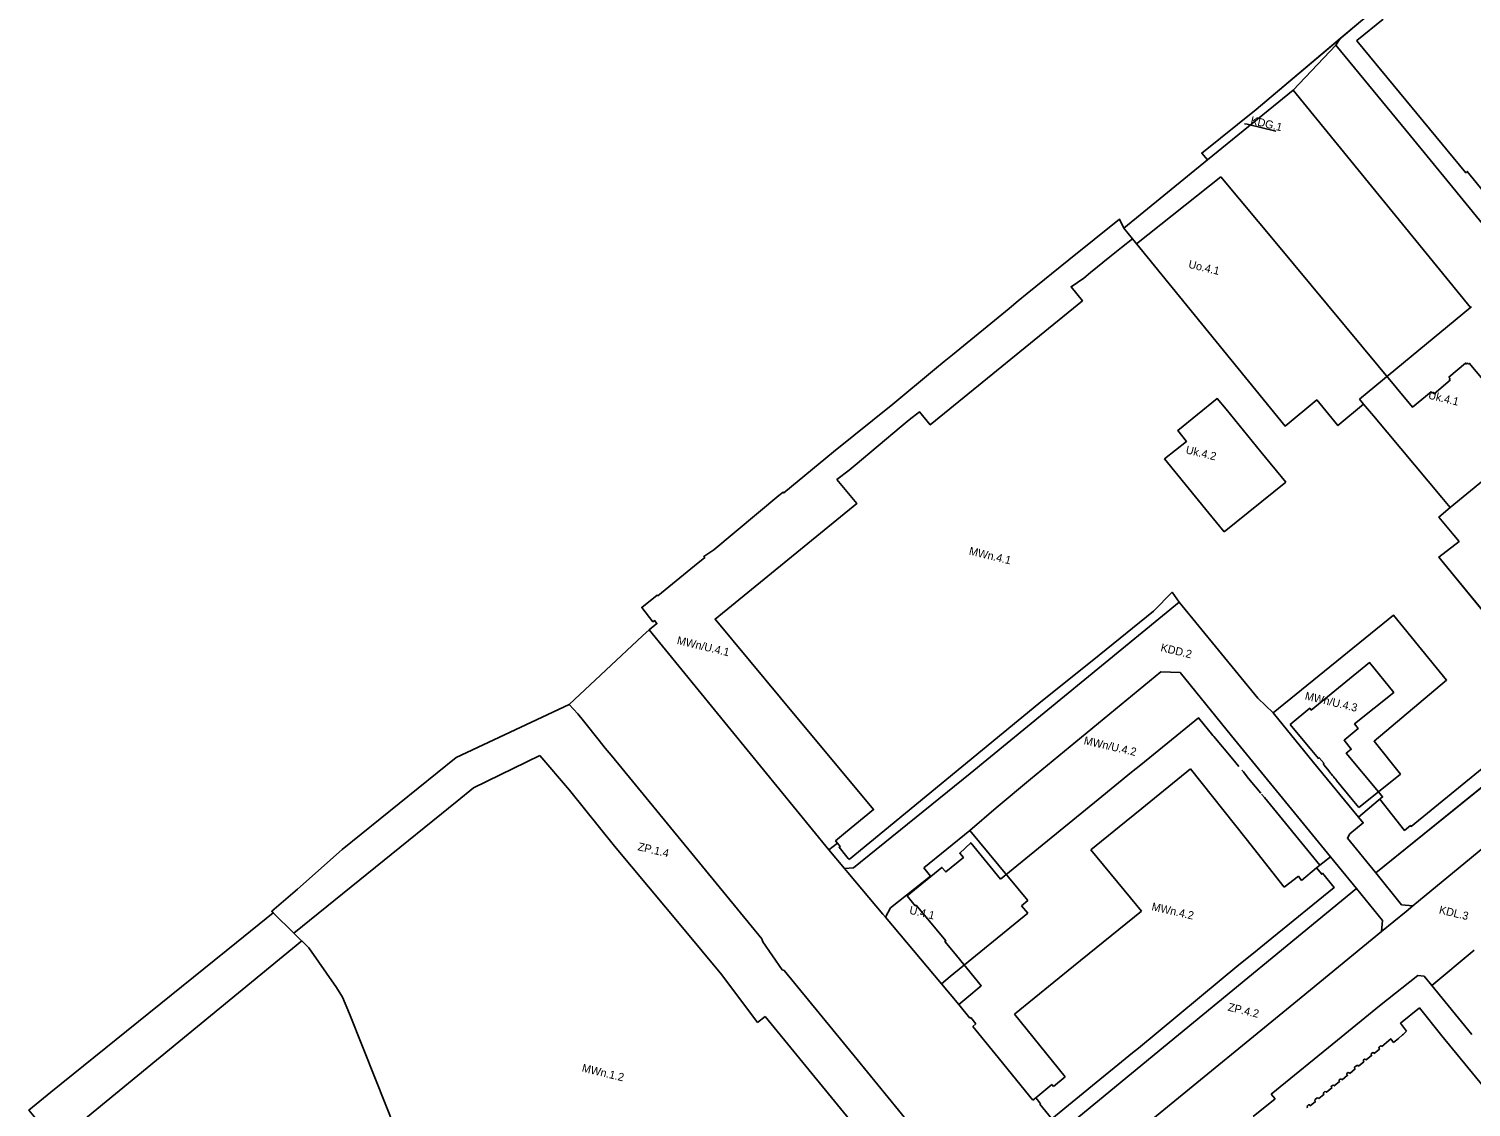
# Model space of a CAD drawing. Extents: x 7429686 to 7432896, y 5547954 to 5550600.
# Drawn here: x 7430132 to 7430853, y 5549462 to 5550001 of the extents above; entities that cross this region are included whole.
import ezdxf

# ---------------------------------------------------------------- set-up
doc = ezdxf.new("R2010")
doc.units = 0
for name, color, linetype in [('granica planu', 7, 'Continuous'), ('linie rozgraniczające', 7, 'Continuous'), ('obowiązująca linia zabudowy', 7, 'Continuous'), ('oznaczenia przeznaczeń', 7, 'Continuous')]:
    doc.layers.add(name, color=color, linetype=linetype)

msp = doc.modelspace()

# ---------------------------------------------------------------- linework, layer by layer
at = {"layer": 'granica planu'}
for p, q in [((7430679.88, 5549901.24), (7430721.7, 5549935.43)), ((7430721.7, 5549935.43), (7430718.8, 5549938.87)), ((7430652.39, 5549885.51), (7430677.58, 5549905.8)), ((7430677.58, 5549905.8), (7430679.88, 5549901.24)), ((7430623.59, 5549862.1), (7430627, 5549864.89)), ((7430594.17, 5549837.99), (7430622.47, 5549861.18)), ((7430622.47, 5549861.18), (7430623.59, 5549862.1)), ((7430589.98, 5549834.54), (7430594.17, 5549837.99)), ((7430534.74, 5549789.36), (7430564.34, 5549813.28)), ((7430509.79, 5549768.85), (7430534.74, 5549789.36)), ((7430509.45, 5549769.31), (7430509.79, 5549768.85)), ((7430474.76, 5549740.46), (7430507.29, 5549767.5)), ((7430469.8, 5549737.01), (7430474.76, 5549740.46)), ((7430445.21, 5549704.96), (7430444.4, 5549704.41)), ((7430345.97, 5549636.49), (7430402.43, 5549663.1))]:
    msp.add_line(p, q, dxfattribs=at)
for points in [[(7430718.8, 5549938.87), (7430746.03, 5549960.72), (7430798.13, 5550004.59), (7430923.69, 5550106.91), (7431051.87, 5550217.85), (7431132.58, 5550281.48)], [(7430627, 5549864.89), (7430631.48, 5549868.55), (7430652.39, 5549885.51)], [(7430564.34, 5549813.28), (7430585.18, 5549830.6), (7430589.98, 5549834.54)], [(7430507.29, 5549767.5), (7430507.35, 5549767.54), (7430509.45, 5549769.31)], [(7430465.23, 5549732.34), (7430470.33, 5549736.47), (7430469.8, 5549737.01)], [(7430444.4, 5549704.41), (7430438.78, 5549711.57), (7430446.42, 5549717.73), (7430446.76, 5549717.38), (7430465.23, 5549732.34)], [(7430442.54, 5549700.35), (7430446.41, 5549703.48), (7430445.21, 5549704.96)], [(7430402.43, 5549663.1), (7430439.12, 5549697.39), (7430442.54, 5549700.35)], [(7430266.62, 5549570.67), (7430289.05, 5549590.5), (7430336.45, 5549628.86), (7430345.97, 5549636.49)], [(7430236.2, 5549543.95), (7430254.55, 5549558.75), (7430253.79, 5549559.57), (7430266.62, 5549570.67)], [(7430132.35, 5549460.15), (7430143.42, 5549469.09), (7430236.2, 5549543.95)]]:
    msp.add_lwpolyline(points, dxfattribs=at)
at = {"layer": 'linie rozgraniczające'}
for p, q in [((7430672.89, 5549886.9), (7430663.09, 5549879.13)), ((7430663.09, 5549879.13), (7430659.85, 5549876.29)), ((7430659.1, 5549864.98), (7430583.08, 5549802.87)), ((7430700.22, 5549785.83), (7430722.36, 5549758.75)), ((7430545.48, 5549782.66), (7430542.42, 5549780.28)), ((7430760.78, 5549774.19), (7430729.96, 5549749.47)), ((7430729.96, 5549749.47), (7430760.78, 5549774.19)), ((7430546.31, 5549763.55), (7430475.46, 5549705.76)), ((7430729.96, 5549749.47), (7430722.36, 5549758.75)), ((7430722.36, 5549758.75), (7430729.96, 5549749.47)), ((7430837.33, 5549756.8), (7430843.03, 5549761.55)), ((7430844.84, 5549747.74), (7430837.33, 5549756.8)), ((7430847.43, 5549744.63), (7430844.84, 5549747.74)), ((7430837.38, 5549736.73), (7430847.43, 5549744.63)), ((7430897.36, 5549663.3), (7430837.38, 5549736.73)), ((7430508.16, 5549666.42), (7430554.71, 5549610.46)), ((7430805.78, 5549578.76), (7430902.46, 5549657.05)), ((7430554.71, 5549610.46), (7430540.68, 5549599.07)), ((7430536.73, 5549593.64), (7430532.29, 5549590.32)), ((7430532.29, 5549590.32), (7430540.19, 5549580.93))]:
    msp.add_line(p, q, dxfattribs=at)
for points in [[(7430973.53, 5550150.05), (7430923.69, 5550106.91), (7430798.13, 5550004.59), (7430788.04, 5549996.1)], [(7430788.04, 5549996.1), (7430746.03, 5549960.72), (7430718.8, 5549938.87), (7430721.7, 5549935.43)], [(7430764.45, 5549970.37), (7430785.78, 5549992.89)], [(7430785.78, 5549992.89), (7430787.7, 5549995.61)], [(7430823.15, 5549947.46), (7430785.78, 5549992.89)], [(7430787.7, 5549995.61), (7430788.04, 5549996.1)], [(7430764.45, 5549970.37), (7430721.7, 5549935.43)], [(7430853.19, 5549861.61), (7430764.45, 5549970.37)], [(7430842.76, 5549923.45), (7430823.15, 5549947.46)], [(7430721.7, 5549935.43), (7430679.88, 5549901.24)], [(7430895.54, 5549859.01), (7430842.76, 5549923.45)], [(7430679.88, 5549901.24), (7430677.58, 5549905.8), (7430652.39, 5549885.51), (7430631.48, 5549868.55), (7430627, 5549864.89), (7430623.59, 5549862.1), (7430622.47, 5549861.18), (7430594.17, 5549837.99), (7430589.98, 5549834.54), (7430585.18, 5549830.6), (7430564.34, 5549813.28), (7430534.74, 5549789.36), (7430509.79, 5549768.85), (7430509.45, 5549769.31), (7430507.35, 5549767.54), (7430507.29, 5549767.5), (7430474.76, 5549740.46), (7430469.8, 5549737.01), (7430470.33, 5549736.47), (7430465.23, 5549732.34), (7430446.76, 5549717.38), (7430446.42, 5549717.73), (7430438.78, 5549711.57), (7430444.4, 5549704.41), (7430445.21, 5549704.96), (7430446.41, 5549703.48), (7430442.54, 5549700.35)], [(7430684.14, 5549896), (7430679.88, 5549901.24)], [(7430532.29, 5549590.32), (7430536.73, 5549593.64), (7430535.72, 5549594.81), (7430540.68, 5549599.07), (7430554.71, 5549610.46), (7430508.16, 5549666.42), (7430492.64, 5549685.07), (7430475.46, 5549705.76), (7430546.31, 5549763.55), (7430536.39, 5549775.56), (7430542.42, 5549780.28), (7430545.48, 5549782.66), (7430568.47, 5549802.15), (7430572.49, 5549805.46), (7430577.72, 5549809.41), (7430583.08, 5549802.87), (7430659.1, 5549864.98), (7430653.43, 5549871.99), (7430659.85, 5549876.29), (7430663.09, 5549879.13), (7430672.89, 5549886.9), (7430678.73, 5549891.62), (7430684.14, 5549896)], [(7430684.14, 5549896), (7430678.73, 5549891.62), (7430672.89, 5549886.9)], [(7430799.73, 5549813.23), (7430786.87, 5549802.53), (7430776.31, 5549815.35), (7430760.42, 5549802.31), (7430684.14, 5549896)], [(7430684.14, 5549896), (7430760.42, 5549802.31)], [(7430659.85, 5549876.29), (7430653.43, 5549871.99), (7430659.1, 5549864.98)], [(7430797.65, 5549815.78), (7430853.19, 5549861.61)], [(7430853.19, 5549861.61), (7430853.71, 5549862.02)], [(7430722.36, 5549758.75), (7430700.22, 5549785.83), (7430711.1, 5549794.65), (7430706.78, 5549800), (7430726.5, 5549816.04), (7430730.95, 5549810.8), (7430748.25, 5549789.4), (7430760.78, 5549774.19)], [(7430760.78, 5549774.19), (7430748.25, 5549789.4), (7430730.95, 5549810.8), (7430726.5, 5549816.04), (7430706.78, 5549800), (7430711.1, 5549794.65), (7430700.22, 5549785.83)], [(7430760.42, 5549802.31), (7430776.31, 5549815.35), (7430786.87, 5549802.53), (7430799.73, 5549813.23)], [(7430799.73, 5549813.23), (7430797.65, 5549815.78)], [(7430843.03, 5549761.55), (7430838.83, 5549766.56), (7430804.68, 5549807.34), (7430799.73, 5549813.23)], [(7430799.73, 5549813.23), (7430804.68, 5549807.34)], [(7430583.08, 5549802.87), (7430577.72, 5549809.41), (7430572.49, 5549805.46), (7430568.47, 5549802.15), (7430545.48, 5549782.66)], [(7430804.68, 5549807.34), (7430838.83, 5549766.56), (7430843.03, 5549761.55)], [(7430843.03, 5549761.55), (7430897.72, 5549806.4)], [(7430542.42, 5549780.28), (7430536.39, 5549775.56), (7430546.31, 5549763.55)], [(7430843.03, 5549761.55), (7430837.33, 5549756.8), (7430844.84, 5549747.74), (7430847.43, 5549744.63), (7430837.38, 5549736.73), (7430897.36, 5549663.3), (7430902.46, 5549657.05)], [(7430754.51, 5549658.77), (7430746.78, 5549666.21), (7430707.47, 5549714.16), (7430602.92, 5549628.54), (7430544.68, 5549581.29), (7430540.19, 5549580.93)], [(7430602.92, 5549628.54), (7430707.47, 5549714.16), (7430746.78, 5549666.21), (7430754.51, 5549658.77)], [(7430475.46, 5549705.76), (7430492.64, 5549685.07), (7430508.16, 5549666.42)], [(7430754.51, 5549658.77), (7430814.61, 5549707.76), (7430841.19, 5549675.26), (7430804.95, 5549644.67), (7430818.12, 5549628.18), (7430807.14, 5549619.41), (7430809.2, 5549616.83), (7430797.14, 5549606.69)], [(7430797.14, 5549606.69), (7430809.2, 5549616.83), (7430807.14, 5549619.41), (7430818.12, 5549628.18), (7430804.95, 5549644.67), (7430841.19, 5549675.26), (7430814.61, 5549707.76), (7430754.51, 5549658.77)], [(7430442.54, 5549700.35), (7430439.12, 5549697.39), (7430402.43, 5549663.1)], [(7430532.29, 5549590.32), (7430442.54, 5549700.35)], [(7430633.19, 5549625.63), (7430698.25, 5549679.36)], [(7430698.25, 5549679.36), (7430707.95, 5549679.01)], [(7430707.95, 5549679.01), (7430733.7, 5549647.43)], [(7430402.43, 5549663.1), (7430345.97, 5549636.49), (7430336.45, 5549628.86), (7430289.05, 5549590.5), (7430266.62, 5549570.67), (7430253.79, 5549559.57), (7430254.55, 5549558.75)], [(7430406.78, 5549658.29), (7430402.43, 5549663.1)], [(7430409.6, 5549654.78), (7430406.78, 5549658.29)], [(7430417.45, 5549645.05), (7430409.6, 5549654.78)], [(7430774.72, 5549634.07), (7430754.51, 5549658.77)], [(7430902.46, 5549657.05), (7430805.78, 5549578.76)], [(7430733.7, 5549647.43), (7430783.08, 5549586.88)], [(7430420.58, 5549641.15), (7430417.45, 5549645.05)], [(7430423.43, 5549637.67), (7430420.58, 5549641.15)], [(7430354.75, 5549621.36), (7430387.85, 5549637.47)], [(7430387.85, 5549637.47), (7430402.68, 5549620.2)], [(7430498.79, 5549545.76), (7430423.43, 5549637.67)], [(7430797.14, 5549606.69), (7430774.72, 5549634.07)], [(7430912.39, 5549634.82), (7430824.34, 5549562.34)], [(7430540.19, 5549580.93), (7430544.68, 5549581.29), (7430602.92, 5549628.54)], [(7430615.95, 5549611.39), (7430633.19, 5549625.63)], [(7430688.8, 5549610.97), (7430713.21, 5549630.8)], [(7430713.21, 5549630.8), (7430740.96, 5549595.8)], [(7430346.52, 5549614.67), (7430354.75, 5549621.36)], [(7430402.68, 5549620.2), (7430425.17, 5549592.2)], [(7430264.83, 5549548.66), (7430346.52, 5549614.67)], [(7430602.84, 5549600), (7430615.95, 5549611.39)], [(7430677.52, 5549601.81), (7430688.8, 5549610.97)], [(7430805.78, 5549578.76), (7430791.63, 5549596.09), (7430792.84, 5549598.31), (7430799.52, 5549603.79), (7430797.14, 5549606.69)], [(7430797.14, 5549606.69), (7430799.52, 5549603.79), (7430792.84, 5549598.31)], [(7430540.68, 5549599.07), (7430535.72, 5549594.81), (7430536.73, 5549593.64)], [(7430579.77, 5549581.32), (7430602.84, 5549600)], [(7430631.91, 5549565.03), (7430602.84, 5549600)], [(7430663.36, 5549590.31), (7430677.52, 5549601.81)], [(7430792.84, 5549598.31), (7430791.63, 5549596.09), (7430805.78, 5549578.76)], [(7430425.17, 5549592.2), (7430459.1, 5549551.42)], [(7430540.19, 5549580.93), (7430532.29, 5549590.32)], [(7430683.19, 5549566.32), (7430663.36, 5549590.31)], [(7430740.96, 5549595.8), (7430760.07, 5549571.68)], [(7430776.24, 5549581.28), (7430777.77, 5549582.71)], [(7430777.77, 5549582.71), (7430783.08, 5549586.88)], [(7430783.08, 5549586.88), (7430796.13, 5549570.96)], [(7430541.83, 5549578.98), (7430540.19, 5549580.93)], [(7430559.28, 5549558.22), (7430541.83, 5549578.98)], [(7430563.2, 5549561.31), (7430583.2, 5549577.1)], [(7430583.2, 5549577.1), (7430579.77, 5549581.32)], [(7430760.07, 5549571.68), (7430767.08, 5549577.09)], [(7430767.08, 5549577.09), (7430768.64, 5549575.04)], [(7430768.64, 5549575.04), (7430776.24, 5549581.28)], [(7430818.73, 5549562.89), (7430805.78, 5549578.76)], [(7430699.66, 5549491.66), (7430796.13, 5549570.96)], [(7430796.13, 5549570.96), (7430809.18, 5549555.04)], [(7430560.63, 5549556.62), (7430563.2, 5549561.31)], [(7430628.68, 5549562.34), (7430631.91, 5549565.03)], [(7430631.78, 5549558.68), (7430628.68, 5549562.34)], [(7430688.7, 5549559.66), (7430683.19, 5549566.32)], [(7430824.34, 5549562.34), (7430818.73, 5549562.89)], [(7430820.95, 5549559.54), (7430824.34, 5549562.34)], [(7430254.55, 5549558.75), (7430236.2, 5549543.95), (7430143.42, 5549469.09), (7430132.35, 5549460.15), (7430171.48, 5549413.08), (7430218.82, 5549376.39)], [(7430264.83, 5549548.66), (7430254.55, 5549558.75)], [(7430560.63, 5549556.62), (7430559.28, 5549558.22)], [(7430588.61, 5549523.36), (7430560.63, 5549556.62)], [(7430592.97, 5549526.92), (7430631.78, 5549558.68)], [(7430654.68, 5549532.07), (7430688.7, 5549559.66)], [(7430808.63, 5549549.4), (7430820.95, 5549559.54)], [(7430809.18, 5549555.04), (7430808.63, 5549549.4)], [(7430272.39, 5549541.24), (7430264.83, 5549548.66)], [(7430459.1, 5549551.42), (7430478.77, 5549527.77)], [(7430499.29, 5549544.37), (7430498.79, 5549545.76)], [(7430768.57, 5549516.43), (7430808.63, 5549549.4)], [(7430286.16, 5549521.39), (7430272.39, 5549541.24)], [(7430509.01, 5549530.32), (7430499.29, 5549544.37)], [(7430833.75, 5549522.41), (7430854.97, 5549540.19)], [(7430625.09, 5549508.07), (7430654.68, 5549532.07)], [(7430478.77, 5549527.77), (7430496.72, 5549503.97)], [(7430509.95, 5549530.04), (7430509.01, 5549530.32)], [(7430546.44, 5549485.44), (7430509.95, 5549530.04)], [(7430588.61, 5549523.36), (7430592.97, 5549526.92)], [(7430807.59, 5549512.27), (7430826.76, 5549527.5)], [(7430826.76, 5549527.5), (7430829.91, 5549527.12)], [(7430829.91, 5549527.12), (7430833.75, 5549522.41)], [(7430289.16, 5549516.58), (7430286.16, 5549521.39)], [(7430292.65, 5549508.21), (7430289.16, 5549516.58)], [(7430597.34, 5549512.98), (7430588.61, 5549523.36)], [(7430853.78, 5549497.92), (7430833.75, 5549522.41)], [(7430602.89, 5549506.15), (7430597.34, 5549512.98)], [(7430694.34, 5549455.8), (7430768.57, 5549516.43)], [(7430786.68, 5549495.19), (7430807.59, 5549512.27)], [(7430305.6, 5549475.67), (7430292.65, 5549508.21)], [(7430496.72, 5549503.97), (7430500.44, 5549507)], [(7430500.44, 5549507), (7430585.7, 5549402.87)], [(7430603.33, 5549506.37), (7430602.89, 5549506.15)], [(7430605.8, 5549503.29), (7430603.33, 5549506.37)], [(7430604.33, 5549501.96), (7430605.8, 5549503.29)], [(7430650.45, 5549476.7), (7430625.09, 5549508.07)], [(7430615.51, 5549488.25), (7430604.33, 5549501.96)], [(7430753.49, 5549468.09), (7430786.68, 5549495.19)], [(7430634.31, 5549465.18), (7430615.51, 5549488.25)], [(7430648.77, 5549449.84), (7430699.66, 5549491.66)], [(7430572.38, 5549453.75), (7430546.44, 5549485.44)], [(7430315.31, 5549451.27), (7430305.6, 5549475.67)], [(7430644.65, 5549471.96), (7430650.45, 5549476.7)], [(7430635.91, 5549466.24), (7430634.31, 5549465.18)], [(7430635.91, 5549466.24), (7430643.89, 5549472.89)], [(7430636.74, 5549465.31), (7430635.91, 5549466.24)], [(7430643.89, 5549472.89), (7430644.65, 5549471.96)], [(7430755.42, 5549465.8), (7430753.49, 5549468.09)], [(7430638.2, 5549463.34), (7430636.74, 5549465.31)], [(7430637.8, 5549463.05), (7430638.2, 5549463.34)], [(7430643.85, 5549455.8), (7430637.8, 5549463.05)], [(7430744.44, 5549457), (7430755.42, 5549465.8)]]:
    msp.add_lwpolyline(points, dxfattribs=at)
at = {"layer": 'obowiązująca linia zabudowy'}
for p, q in [((7430728.27, 5549927), (7430686.2, 5549893.47)), ((7430779.95, 5549632.65), (7430782.29, 5549629.81)), ((7430797.39, 5549611.48), (7430807.14, 5549619.41)), ((7430807.14, 5549619.41), (7430807.14, 5549619.41)), ((7430536.73, 5549593.64), (7430536.73, 5549593.64))]:
    msp.add_line(p, q, dxfattribs=at)
for points in [[(7430809.47, 5550005.9), (7430796.29, 5549995.12), (7430796.34, 5549995.06), (7430850.88, 5549928.94), (7430851.52, 5549929.64), (7430861.12, 5549917.74)], [(7430874.3, 5549807.74), (7430852.44, 5549833.69), (7430851.94, 5549833.28), (7430851.51, 5549833.79), (7430850.98, 5549833.35), (7430850.62, 5549833.79), (7430842.33, 5549826.8), (7430842.97, 5549826.03), (7430842.56, 5549825.69), (7430842.98, 5549825.18), (7430835.05, 5549818.5), (7430834.43, 5549819.23), (7430833.95, 5549818.83), (7430833.47, 5549819.41), (7430824.17, 5549811.71), (7430756.29, 5549893.44), (7430728.27, 5549927)], [(7430667.51, 5549687.76), (7430694.58, 5549709.75), (7430703.96, 5549719.13), (7430707.47, 5549714.16)], [(7430807.75, 5549615.61), (7430820.21, 5549600.01), (7430823.08, 5549602.43), (7430823.42, 5549602.03), (7430938.16, 5549695.73)], [(7430542.48, 5549585.49), (7430637.32, 5549663.59), (7430667.51, 5549687.76)], [(7430807.14, 5549619.41), (7430791.05, 5549638.65), (7430793.52, 5549640.67), (7430789.92, 5549645.1), (7430796.97, 5549650.95), (7430795.17, 5549653.32), (7430814.81, 5549669.03), (7430802.68, 5549683.95), (7430773.56, 5549660.22), (7430772.82, 5549661.13), (7430762.99, 5549653.08)], [(7430724.77, 5549647.09), (7430724.37, 5549647.57), (7430717.08, 5549656.39), (7430688.29, 5549632.9), (7430683.64, 5549629.11), (7430666.97, 5549615.51), (7430618.14, 5549575.68)], [(7430737.32, 5549632.07), (7430734.33, 5549635.71), (7430724.77, 5549647.09)], [(7430762.99, 5549653.08), (7430767.07, 5549648.16), (7430772.95, 5549641.07), (7430777.11, 5549636.05), (7430777.51, 5549636.38), (7430779.96, 5549633.54), (7430779.52, 5549633.18), (7430779.95, 5549632.65)], [(7430748.32, 5549618.64), (7430743.05, 5549625.07), (7430741.55, 5549626.9), (7430739.6, 5549629.28), (7430738.89, 5549630.14)], [(7430782.29, 5549629.81), (7430783.19, 5549628.72), (7430783.33, 5549628.54), (7430783.49, 5549628.35), (7430784.22, 5549627.47), (7430784.42, 5549627.23), (7430784.62, 5549626.98), (7430784.82, 5549626.74), (7430785.02, 5549626.49), (7430785.23, 5549626.25), (7430785.43, 5549626), (7430785.63, 5549625.76), (7430785.83, 5549625.51), (7430786.03, 5549625.27), (7430786.24, 5549625.02), (7430794.06, 5549615.53), (7430797.39, 5549611.48)], [(7430777.77, 5549582.71), (7430750.11, 5549616.45), (7430748.71, 5549618.16)], [(7430536.73, 5549593.64), (7430538.03, 5549592.05), (7430537.49, 5549591.6), (7430541.41, 5549586.8), (7430542.05, 5549586.02), (7430542.48, 5549585.49)], [(7430618.14, 5549575.68), (7430603.3, 5549593.87), (7430597.77, 5549588.7), (7430599.66, 5549586.5), (7430590.78, 5549579.26), (7430588.91, 5549581.49), (7430571.54, 5549567.24), (7430575.56, 5549562.32), (7430575.95, 5549562.64), (7430590.75, 5549544.78), (7430590.33, 5549544.41), (7430594.69, 5549539.31), (7430606.49, 5549524.79), (7430608.55, 5549522.33), (7430601.3, 5549516.29), (7430597.34, 5549512.98)], [(7430753.78, 5549546.06), (7430784.95, 5549571.42), (7430779.19, 5549578.58), (7430778.79, 5549578.15), (7430776.24, 5549581.28)], [(7430265.2, 5549548.31), (7430265.2, 5549548.31)], [(7430265.2, 5549548.31), (7430265.2, 5549548.31)], [(7430684.17, 5549488.72), (7430687.1, 5549491.15), (7430737.36, 5549532.75), (7430744.63, 5549538.6), (7430753.78, 5549546.06)], [(7430268.83, 5549544.74), (7430145.91, 5549443.84)], [(7430859.5, 5549472.18), (7430838.81, 5549497.31), (7430827.62, 5549511.27), (7430818.17, 5549503.55), (7430821.09, 5549499.68)], [(7430821.09, 5549499.68), (7430819.45, 5549498), (7430819.2, 5549497.74), (7430817.08, 5549495.98), (7430814.71, 5549494.02), (7430813.25, 5549495.79), (7430808.76, 5549492.02), (7430808.41, 5549492.32), (7430808.04, 5549492.04), (7430807.43, 5549491.57)], [(7430643.85, 5549455.8), (7430667.83, 5549475.39), (7430675.07, 5549481.21), (7430684.17, 5549488.72)], [(7430807.43, 5549491.57), (7430807.35, 5549491.03), (7430807.66, 5549490.65), (7430804.99, 5549488.49), (7430804.75, 5549488.82), (7430804.31, 5549488.93), (7430803.58, 5549488.47), (7430803.44, 5549487.83), (7430803.71, 5549487.41), (7430800.99, 5549485.23), (7430800.79, 5549485.48), (7430800.14, 5549485.65), (7430799.66, 5549485.29), (7430799.6, 5549484.61), (7430799.83, 5549484.28), (7430797.16, 5549482.1), (7430796.94, 5549482.37), (7430796.27, 5549482.44), (7430795.18, 5549481.59), (7430795.2, 5549481.11), (7430795.47, 5549480.75), (7430792.8, 5549478.45), (7430792.5, 5549478.79), (7430791.93, 5549478.89), (7430791.39, 5549478.46), (7430791.35, 5549477.97), (7430791.66, 5549477.58), (7430788.93, 5549475.32), (7430788.63, 5549475.58), (7430787.96, 5549475.67), (7430787.45, 5549475.26), (7430787.45, 5549474.79), (7430787.73, 5549474.47), (7430785.04, 5549472.23), (7430784.81, 5549472.54), (7430784.11, 5549472.5), (7430783.59, 5549472.13), (7430783.55, 5549471.56), (7430783.83, 5549471.24), (7430781.23, 5549469.04), (7430780.96, 5549469.35), (7430780.32, 5549469.4), (7430779.79, 5549468.98), (7430779.73, 5549468.56), (7430779.72, 5549468.18), (7430779.87, 5549467.94), (7430777.4, 5549465.87), (7430777.13, 5549466.17), (7430776.46, 5549466.2), (7430775.54, 5549465.46), (7430775.39, 5549464.7), (7430775.59, 5549464.4), (7430773.07, 5549462.34), (7430772.79, 5549462.72), (7430772.23, 5549462.83), (7430771.62, 5549462.32), (7430771.53, 5549461.6), (7430771.73, 5549461.33)]]:
    msp.add_lwpolyline(points, dxfattribs=at)
at = {"layer": 'oznaczenia przeznaczeń'}
msp.add_lwpolyline([(7430755.76, 5549949.86), (7430741.45, 5549953.29), (7430740.09, 5549953.49)], dxfattribs=at)

# ---------------------------------------------------------------- texts
for s, rotation, p in [('KDG.1', 346.4891, (7430742.89, 5549953.49)), ('Uo.4.1', 346.51221, (7430711.85, 5549881.53)), ('Uk.4.1', 346.4891, (7430831.78, 5549816.07)), ('Uk.4.2', 346.4891, (7430710.52, 5549788.68)), ('MWn.4.1', 346.4891, (7430602.14, 5549738.08)), ('MWn/U.4.1', 346.4891, (7430456.11, 5549693.36)), ('KDD.2', 346.4891, (7430697.96, 5549689.76)), ('MWn/U.4.3', 346.4891, (7430770.09, 5549665.58)), ('MWn/U.4.2', 347.06089, (7430659.55, 5549643.23)), ('ZP.1.4', 346.4891, (7430436.53, 5549590.2)), ('U.4.1', 346.4891, (7430572.31, 5549558.4)), ('MWn.4.2', 347.06089, (7430693.45, 5549560.17)), ('KDL.3', 346.4891, (7430837.15, 5549558.59)), ('ZP.4.2', 346.4891, (7430731.56, 5549509.94)), ('MWn.1.2', 346.4891, (7430408.59, 5549479.46))]:
    msp.add_text(s, height=4, rotation=rotation, dxfattribs=at).set_placement(p)

doc.saveas('drawing.dxf')
